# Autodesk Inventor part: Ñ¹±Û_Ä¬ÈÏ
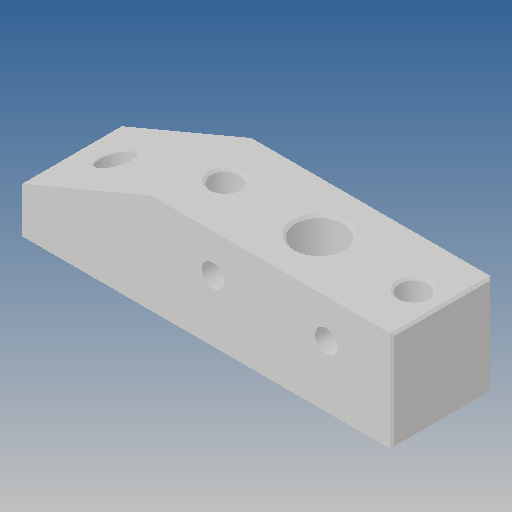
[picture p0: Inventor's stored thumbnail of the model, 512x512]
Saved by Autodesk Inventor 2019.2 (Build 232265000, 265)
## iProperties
Created: 2011-12
Part Number: Ñ¹±Û_Ä¬ÈÏ
Material: Ogólny
Document SubType Name: Modeling
Designer: CADENGINEERING4
Density: 1 g/cm^3
Appearance: Domyślna
Author: CADENGINEERING4
Revision Number: ÈÎºÎ
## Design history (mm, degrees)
feature "NONE"
node "Bryła1"
